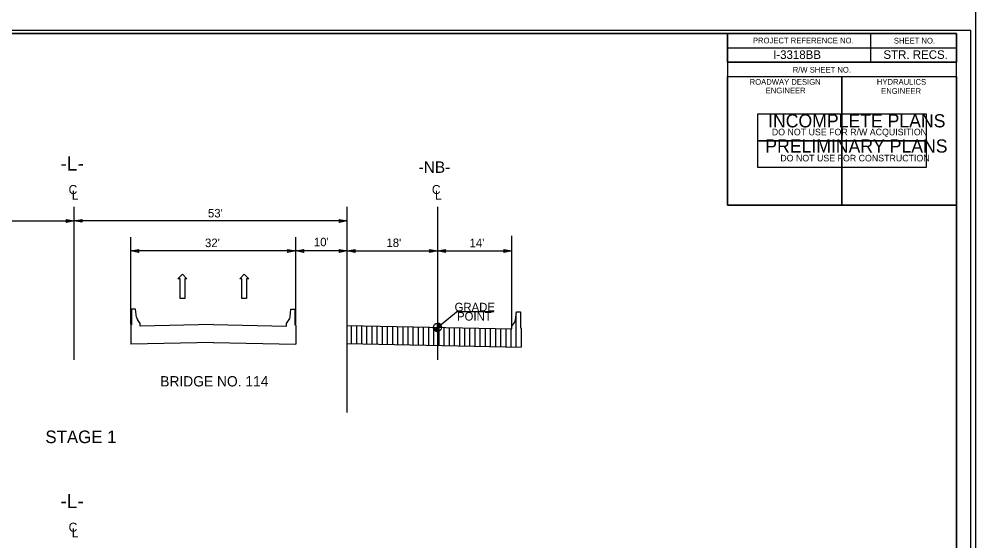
# Model space of a CAD drawing. Extents: x 2241081 to 2251104, y 658534 to 663427.
# Drawn here: x 2248483 to 2249319, y 659163 to 659619 of the extents above; entities that cross this region are included whole.
import ezdxf

# ---------------------------------------------------------------- set-up
doc = ezdxf.new("R2010")
doc.units = 0
for name, color, linetype in [('Prop Dimension Text', 7, 'Continuous'), ('Prop Lane Arrow CELL', 7, 'Continuous'), ('Prop Roadway Bridge', 7, 'Continuous'), ('Sheet Data Field CELL', 7, 'Continuous'), ('Sheet Plan CELL', 7, 'Continuous'), ('Sheet Plot Border Inside CELL', 7, 'Continuous'), ('Sheet Plot Border Outside CELL', 7, 'Continuous'), ('Sheet Sticker Incomplete CELL', 7, 'Continuous'), ('Sheet Sticker Preliminary CELL', 7, 'Continuous'), ('Typical Grade Point Symbol CELL', 7, 'Continuous'), ('Typical Terminator CELL', 7, 'Continuous'), ('Typical Text Centerline CELL', 7, 'Continuous'), ('Typical Text Grade Point CELL', 7, 'Continuous'), ('Typical Text Label CELL', 7, 'Continuous')]:
    doc.layers.add(name, color=color, linetype=linetype)

msp = doc.modelspace()

# ---------------------------------------------------------------- linework, layer by layer
at = {"layer": 'Prop Dimension Text'}
for p, q in [((2248769.6, 659351.53), (2248769.6, 659455.33)), ((2248310.6, 659442.91), (2248531.1, 659442.91)), ((2248769.6, 659442.91), (2248531.1, 659442.91)), ((2248580.6, 659352.28), (2248580.6, 659428.7)), ((2248724.6, 659352.28), (2248724.6, 659428.7)), ((2248913.6, 659351.23), (2248913.6, 659430.01)), ((2248724.6, 659416.65), (2248580.6, 659416.65)), ((2248769.6, 659416.65), (2248724.6, 659416.65)), ((2248769.6, 659416.65), (2248848.55, 659416.65)), ((2248848.55, 659416.65), (2248913.6, 659416.65)), ((2248917.42, 659332.79), (2248917.42, 659362.54)), ((2248769.6, 659275.49), (2248769.6, 659351.53)), ((2248773.42, 659335.79), (2248773.42, 659351.45)), ((2248777.92, 659335.69), (2248777.92, 659351.36)), ((2248782.42, 659335.6), (2248782.42, 659351.26)), ((2248786.92, 659335.51), (2248786.92, 659351.17)), ((2248791.42, 659335.41), (2248791.42, 659351.08)), ((2248795.92, 659335.32), (2248795.92, 659350.98)), ((2248800.42, 659335.23), (2248800.42, 659350.89)), ((2248804.92, 659335.13), (2248804.92, 659350.8)), ((2248809.42, 659335.04), (2248809.42, 659350.7)), ((2248813.92, 659334.95), (2248813.92, 659350.61)), ((2248818.42, 659334.85), (2248818.42, 659350.52)), ((2248822.92, 659334.76), (2248822.92, 659350.42)), ((2248827.42, 659334.66), (2248827.42, 659350.33)), ((2248831.92, 659334.57), (2248831.92, 659350.23)), ((2248836.42, 659334.48), (2248836.42, 659350.14)), ((2248840.92, 659334.38), (2248840.92, 659350.05)), ((2248845.42, 659334.29), (2248845.42, 659349.95)), ((2248849.92, 659334.2), (2248849.92, 659349.86)), ((2248854.42, 659334.1), (2248854.42, 659349.77)), ((2248858.92, 659334.01), (2248858.92, 659349.67)), ((2248863.42, 659333.92), (2248863.42, 659349.58)), ((2248867.92, 659333.82), (2248867.92, 659349.49)), ((2248872.42, 659333.73), (2248872.42, 659349.39)), ((2248876.92, 659333.63), (2248876.92, 659349.3)), ((2248881.42, 659333.54), (2248881.42, 659349.21)), ((2248885.92, 659333.45), (2248885.92, 659349.11)), ((2248890.42, 659333.35), (2248890.42, 659349.02)), ((2248894.92, 659333.26), (2248894.92, 659348.92)), ((2248899.42, 659333.17), (2248899.42, 659348.83)), ((2248903.92, 659333.07), (2248903.92, 659348.74)), ((2248908.42, 659332.98), (2248908.42, 659348.64)), ((2248912.92, 659332.89), (2248912.92, 659348.55))]:
    msp.add_line(p, q, dxfattribs=at)
at = {"layer": 'Prop Lane Arrow CELL'}
for p, q in [((2248621.75, 659392.35), (2248625.6, 659396.26)), ((2248623.61, 659392.35), (2248621.75, 659392.35)), ((2248623.61, 659374.99), (2248623.61, 659392.35)), ((2248625.6, 659396.26), (2248629.57, 659392.35)), ((2248629.57, 659392.35), (2248627.71, 659392.35)), ((2248627.71, 659392.35), (2248627.71, 659374.99)), ((2248675.75, 659392.35), (2248679.6, 659396.26)), ((2248677.61, 659392.35), (2248675.75, 659392.35)), ((2248677.61, 659374.99), (2248677.61, 659392.35)), ((2248679.6, 659396.26), (2248683.57, 659392.35)), ((2248683.57, 659392.35), (2248681.71, 659392.35)), ((2248681.71, 659392.35), (2248681.71, 659374.99)), ((2248627.71, 659374.99), (2248623.61, 659374.99)), ((2248681.71, 659374.99), (2248677.61, 659374.99))]:
    msp.add_line(p, q, dxfattribs=at)
at = {"layer": 'Prop Roadway Bridge'}
for p, q in [((2248581.42, 659365.89), (2248581.25, 659365.73)), ((2248581.25, 659365.73), (2248581.25, 659351.96)), ((2248584.57, 659365.89), (2248581.42, 659365.89)), ((2248584.76, 659365.71), (2248584.57, 659365.89)), ((2248585.49, 659358.74), (2248584.76, 659365.71)), ((2248719.71, 659358.74), (2248720.44, 659365.71)), ((2248720.44, 659365.71), (2248720.62, 659365.89)), ((2248720.62, 659365.89), (2248723.78, 659365.89)), ((2248723.78, 659365.89), (2248723.95, 659365.73)), ((2248723.95, 659365.73), (2248723.95, 659351.96)), ((2248916.77, 659356.33), (2248917.5, 659363.3)), ((2248917.5, 659363.3), (2248917.68, 659363.48)), ((2248917.68, 659363.48), (2248920.84, 659363.48)), ((2248920.84, 659363.48), (2248921, 659363.32)), ((2248921, 659363.32), (2248921, 659349.54)), ((2248580.93, 659351.96), (2248580.6, 659351.63)), ((2248580.6, 659351.63), (2248580.6, 659349.34)), ((2248581.25, 659351.96), (2248580.93, 659351.96)), ((2248588.66, 659353.26), (2248586.25, 659356.7)), ((2248588.66, 659350.95), (2248588.66, 659353.26)), ((2248652.6, 659352.28), (2248588.66, 659350.95)), ((2248652.6, 659352.28), (2248716.54, 659350.95)), ((2248716.54, 659353.26), (2248718.94, 659356.7)), ((2248716.54, 659350.95), (2248716.54, 659353.26)), ((2248723.95, 659351.96), (2248724.27, 659351.96)), ((2248724.27, 659351.96), (2248724.6, 659351.63)), ((2248724.6, 659351.63), (2248724.6, 659349.34)), ((2248769.6, 659351.53), (2248913.6, 659348.54)), ((2248913.6, 659350.85), (2248916, 659354.28)), ((2248913.6, 659348.54), (2248913.6, 659350.85)), ((2248921, 659349.54), (2248921.33, 659349.54)), ((2248921.33, 659349.54), (2248921.66, 659349.22)), ((2248580.6, 659349.34), (2248580.6, 659335.12)), ((2248724.6, 659349.34), (2248724.6, 659335.12)), ((2248921.66, 659349.22), (2248921.66, 659346.93)), ((2248921.66, 659346.93), (2248921.66, 659332.7)), ((2248652.92, 659336.62), (2248580.6, 659335.12)), ((2248652.6, 659336.61), (2248724.6, 659335.12)), ((2248769.6, 659335.87), (2248921.66, 659332.7))]:
    msp.add_line(p, q, dxfattribs=at)
for centre, start, end in [((2248589.82, 659359.19), 186.011, 214.99123), ((2248715.38, 659359.19), 325.00863, 353.98887), ((2248912.43, 659356.78), 325.00863, 353.98887)]:
    msp.add_arc(centre, 4.36, start, end, dxfattribs=at)
at = {"layer": 'Sheet Plan CELL'}
for p, q in [((2249226.97, 659606.71), (2249227.02, 659581.71)), ((2249101.94, 659594.24), (2249301.99, 659594.23)), ((2249101.96, 659581.7), (2249301.99, 659581.73)), ((2249101.96, 659581.7), (2249301.99, 659581.73)), ((2249101.96, 659581.7), (2249101.96, 659569.21)), ((2249202.01, 659569.21), (2249202.02, 659456.75))]:
    msp.add_line(p, q, dxfattribs=at)
for points in [[(2247801.99, 658556.78), (2247801.97, 659606.75), (2249101.96, 659606.79), (2249101.97, 659456.73), (2249302.01, 659456.71), (2249302, 658556.78)], [(2249302.03, 659606.78), (2247801.99, 659606.78), (2247801.99, 658556.78), (2249302, 658556.78)], [(2249101.96, 659606.79), (2249302.03, 659606.78), (2249301.99, 659581.73), (2249101.96, 659581.7)], [(2249101.96, 659569.21), (2249202.01, 659569.21), (2249202.01, 659456.7), (2249101.97, 659456.73)], [(2249202.01, 659569.21), (2249301.99, 659569.23), (2249302.01, 659456.71), (2249202.01, 659456.7)]]:
    msp.add_lwpolyline(points, close=True, dxfattribs=at)
at = {"layer": 'Sheet Plot Border Inside CELL'}
msp.add_lwpolyline([(2247648.5, 658554.27), (2249314.49, 658554.28), (2249314.51, 659609.26), (2247648.51, 659609.27)], close=True, dxfattribs=at)
at = {"layer": 'Sheet Plot Border Outside CELL'}
msp.add_lwpolyline([(2247635.5, 658534.27), (2249319, 658534.26), (2249319.01, 659629.26), (2247635.51, 659629.27)], close=True, dxfattribs=at)
at = {"layer": 'Sheet Sticker Incomplete CELL'}
msp.add_lwpolyline([(2249128.51, 659512.96), (2249128.51, 659536.46), (2249275.51, 659536.46), (2249275.51, 659512.96)], close=True, dxfattribs=at)
at = {"layer": 'Sheet Sticker Preliminary CELL'}
msp.add_lwpolyline([(2249128.51, 659489.46), (2249128.51, 659512.96), (2249275.51, 659512.96), (2249275.51, 659489.46)], close=True, dxfattribs=at)
at = {"layer": 'Typical Grade Point Symbol CELL'}
for p, q in [((2248848.55, 659349.89), (2248865.24, 659363.34)), ((2248844.97, 659349.89), (2248848.55, 659349.89)), ((2248848.55, 659353.47), (2248848.55, 659349.89)), ((2248848.55, 659349.89), (2248848.55, 659353.47)), ((2248848.55, 659349.89), (2248848.55, 659346.31)), ((2248852.13, 659349.89), (2248848.55, 659349.89))]:
    msp.add_line(p, q, dxfattribs=at)
for points in [[(2248845.01, 659349.38), (2248845.01, 659349.89)], [(2248845.08, 659349.01), (2248845.08, 659349.89)], [(2248845.15, 659348.77), (2248845.15, 659349.89)], [(2248845.22, 659348.57), (2248845.22, 659349.89)], [(2248845.29, 659348.4), (2248845.29, 659349.89)], [(2248845.36, 659348.25), (2248845.36, 659349.89)], [(2248845.44, 659348.12), (2248845.44, 659349.89)], [(2248845.51, 659348), (2248845.51, 659349.89)], [(2248845.58, 659347.89), (2248845.58, 659349.89)], [(2248845.65, 659347.79), (2248845.65, 659349.89)], [(2248845.72, 659347.69), (2248845.72, 659349.89)], [(2248845.79, 659347.61), (2248845.79, 659349.89)], [(2248845.87, 659347.52), (2248845.87, 659349.89)], [(2248845.94, 659347.44), (2248845.94, 659349.89)], [(2248846.01, 659347.37), (2248846.01, 659349.89)], [(2248846.08, 659347.29), (2248846.08, 659349.89)], [(2248846.15, 659347.23), (2248846.15, 659349.89)], [(2248846.22, 659347.17), (2248846.22, 659349.89)], [(2248846.29, 659347.1), (2248846.29, 659349.89)], [(2248846.37, 659347.05), (2248846.37, 659349.89)], [(2248846.44, 659347), (2248846.44, 659349.89)], [(2248846.51, 659346.95), (2248846.51, 659349.89)], [(2248846.58, 659346.9), (2248846.58, 659349.89)], [(2248846.65, 659346.85), (2248846.65, 659349.89)], [(2248846.72, 659346.81), (2248846.72, 659349.89)], [(2248846.8, 659346.77), (2248846.8, 659349.89)], [(2248846.87, 659346.73), (2248846.87, 659349.89)], [(2248846.94, 659346.69), (2248846.94, 659349.89)], [(2248847.01, 659346.66), (2248847.01, 659349.89)], [(2248847.08, 659346.63), (2248847.08, 659349.89)], [(2248847.15, 659346.59), (2248847.15, 659349.89)], [(2248847.23, 659346.56), (2248847.23, 659349.89)], [(2248847.3, 659346.53), (2248847.3, 659349.89)], [(2248847.37, 659346.51), (2248847.37, 659349.89)], [(2248847.44, 659346.48), (2248847.44, 659349.89)], [(2248847.51, 659346.46), (2248847.51, 659349.89)], [(2248847.58, 659346.44), (2248847.58, 659349.89)], [(2248847.66, 659346.42), (2248847.66, 659349.89)], [(2248847.73, 659346.4), (2248847.73, 659349.89)], [(2248847.8, 659346.39), (2248847.8, 659349.89)], [(2248847.87, 659346.37), (2248847.87, 659349.89)], [(2248847.94, 659346.36), (2248847.94, 659349.89)], [(2248848.01, 659346.35), (2248848.01, 659349.89)], [(2248848.09, 659346.34), (2248848.09, 659349.89)], [(2248848.16, 659346.33), (2248848.16, 659349.89)], [(2248848.23, 659346.32), (2248848.23, 659349.89)], [(2248848.3, 659346.32), (2248848.3, 659349.89)], [(2248848.37, 659346.32), (2248848.37, 659349.89)], [(2248848.44, 659346.31), (2248848.44, 659349.89)], [(2248848.51, 659346.31), (2248848.51, 659346.31), (2248848.51, 659349.89)], [(2248848.6, 659349.89), (2248848.6, 659353.47), (2248848.6, 659353.47)], [(2248848.67, 659349.89), (2248848.67, 659353.47)], [(2248848.75, 659349.89), (2248848.75, 659353.46)], [(2248848.82, 659349.89), (2248848.82, 659353.46)], [(2248848.89, 659349.89), (2248848.89, 659353.45)], [(2248848.96, 659349.89), (2248848.96, 659353.45)], [(2248849.03, 659349.89), (2248849.03, 659353.44)], [(2248849.1, 659349.89), (2248849.1, 659353.42)], [(2248849.18, 659349.89), (2248849.18, 659353.41)], [(2248849.25, 659349.89), (2248849.25, 659353.4)], [(2248849.32, 659349.89), (2248849.32, 659353.38)], [(2248849.39, 659349.89), (2248849.39, 659353.37)], [(2248849.46, 659349.89), (2248849.46, 659353.35)], [(2248849.53, 659349.89), (2248849.53, 659353.33)], [(2248849.61, 659349.89), (2248849.61, 659353.31)], [(2248849.68, 659349.89), (2248849.68, 659353.29)], [(2248849.75, 659349.89), (2248849.75, 659353.26)], [(2248849.82, 659349.89), (2248849.82, 659353.24)], [(2248849.89, 659349.89), (2248849.89, 659353.21)], [(2248849.96, 659349.89), (2248849.96, 659353.18)], [(2248850.03, 659349.89), (2248850.03, 659353.14)], [(2248850.11, 659349.89), (2248850.11, 659353.11)], [(2248850.18, 659349.89), (2248850.18, 659353.08)], [(2248850.25, 659349.89), (2248850.25, 659353.04)], [(2248850.32, 659349.89), (2248850.32, 659353)], [(2248850.39, 659349.89), (2248850.39, 659352.96)], [(2248850.46, 659349.89), (2248850.46, 659352.91)], [(2248850.54, 659349.89), (2248850.54, 659352.86)], [(2248850.61, 659349.89), (2248850.61, 659352.82)], [(2248850.68, 659349.89), (2248850.68, 659352.77)], [(2248850.75, 659349.89), (2248850.75, 659352.71)], [(2248850.82, 659349.89), (2248850.82, 659352.66)], [(2248850.89, 659349.89), (2248850.89, 659352.59)], [(2248850.97, 659349.89), (2248850.97, 659352.53)], [(2248851.04, 659349.89), (2248851.04, 659352.47)], [(2248851.11, 659349.89), (2248851.11, 659352.4)], [(2248851.18, 659349.89), (2248851.18, 659352.32)], [(2248851.25, 659349.89), (2248851.25, 659352.24)], [(2248851.32, 659349.89), (2248851.32, 659352.15)], [(2248851.4, 659349.89), (2248851.4, 659352.06)], [(2248851.47, 659349.89), (2248851.47, 659351.97)], [(2248851.54, 659349.89), (2248851.54, 659351.86)], [(2248851.61, 659349.89), (2248851.61, 659351.75)], [(2248851.68, 659349.89), (2248851.68, 659351.62)], [(2248851.75, 659349.89), (2248851.75, 659351.49)], [(2248851.83, 659349.89), (2248851.83, 659351.34)], [(2248851.9, 659349.89), (2248851.9, 659351.17)], [(2248851.97, 659349.89), (2248851.97, 659350.96)], [(2248852.04, 659349.89), (2248852.04, 659350.7)], [(2248852.11, 659349.89), (2248852.11, 659350.28)]]:
    msp.add_lwpolyline(points, dxfattribs=at)
msp.add_circle((2248848.55, 659349.89), 3.58, dxfattribs=at)
for start, end in [(179.99048, 269.99048), (359.99048, 89.99048)]:
    msp.add_arc((2248848.55, 659349.89), 3.58, start, end, dxfattribs=at)
at = {"layer": 'Typical Terminator CELL'}
for points in [[(2248524.07, 659444.12), (2248531.1, 659442.91), (2248524.03, 659441.66), (2248524.93, 659442.91)], [(2248538.13, 659441.7), (2248531.1, 659442.91), (2248538.17, 659444.16), (2248537.27, 659442.91)], [(2248762.57, 659444.12), (2248769.6, 659442.91), (2248762.53, 659441.66), (2248763.43, 659442.91)], [(2248587.63, 659415.43), (2248580.6, 659416.65), (2248587.67, 659417.9), (2248586.77, 659416.65)], [(2248717.57, 659417.86), (2248724.6, 659416.65), (2248717.53, 659415.4), (2248718.43, 659416.65)], [(2248731.63, 659415.43), (2248724.6, 659416.65), (2248731.67, 659417.9), (2248730.77, 659416.65)], [(2248762.57, 659417.86), (2248769.6, 659416.65), (2248762.53, 659415.4), (2248763.43, 659416.65)], [(2248776.63, 659415.43), (2248769.6, 659416.65), (2248776.67, 659417.9), (2248775.77, 659416.65)], [(2248841.52, 659417.86), (2248848.55, 659416.65), (2248841.48, 659415.4), (2248842.38, 659416.65)], [(2248855.58, 659415.43), (2248848.55, 659416.65), (2248855.62, 659417.9), (2248854.72, 659416.65)], [(2248906.57, 659417.86), (2248913.6, 659416.65), (2248906.53, 659415.4), (2248907.43, 659416.65)]]:
    msp.add_lwpolyline(points, close=True, dxfattribs=at)
at = {"layer": 'Typical Text Centerline CELL'}
for p, q in [((2248531.1, 659321.64), (2248531.1, 659455.33)), ((2248848.55, 659455.33), (2248848.55, 659321.64))]:
    msp.add_line(p, q, dxfattribs=at)
at = {"layer": 'Typical Text Grade Point CELL'}
msp.add_line((2248897.75, 659363.34), (2248865.24, 659363.34), dxfattribs=at)

# ---------------------------------------------------------------- texts
at = {"layer": 'Prop Dimension Text'}
for s, height, rotation, p in [('-L-', 12.5, 0.03489, (2248519.02, 659486.96)), ('-NB-', 10.024, 0.03489, (2248832.13, 659484.91)), ("53'", 7.425, 359.99993, (2248647.94, 659445.95)), ("32'", 7.425, 359.99993, (2248645.38, 659420.01)), ("10'", 7.425, 359.99993, (2248740.55, 659420.77)), ("18'", 7.425, 359.99993, (2248803.94, 659420.06)), ("14'", 7.425, 359.99993, (2248876.57, 659419.91)), ('BRIDGE NO. 114', 9.0214, 359.99993, (2248606.24, 659298.23)), ('-L-', 12.5, 0.03489, (2248519.02, 659191.86))]:
    msp.add_text(s, height=height, rotation=rotation, dxfattribs=at).set_placement(p)
at = {"layer": 'Sheet Data Field CELL'}
for s, p in [('I-3318BB', (2249141.83, 659584.46)), ('STR. RECS.', (2249238.26, 659584.53))]:
    msp.add_text(s, height=7.5, rotation=359.99994, dxfattribs=at).set_placement(p)
at = {"layer": 'Sheet Plan CELL'}
for s, height, p in [('PROJECT REFERENCE NO.', 5.0001, (2249124.16, 659598.06)), ('SHEET NO.', 5, (2249247.32, 659597.95)), ('R/W SHEET NO.', 5.0001, (2249158.96, 659572.51)), ('ROADWAY DESIGN', 5.0001, (2249121.33, 659561.91)), ('HYDRAULICS', 5, (2249232.47, 659561.94)), ('ENGINEER', 5, (2249135.32, 659554.38)), ('ENGINEER', 5, (2249236.23, 659553.98))]:
    msp.add_text(s, height=height, rotation=359.99994, dxfattribs=at).set_placement(p)
at = {"layer": 'Sheet Sticker Incomplete CELL'}
for s, height, p in [('INCOMPLETE PLANS', 11.52, (2249137.46, 659524.66)), ('DO NOT USE FOR R/W ACQUISITION', 5.76, (2249140.71, 659517.71))]:
    msp.add_text(s, height=height, rotation=359.99993, dxfattribs=at).set_placement(p)
at = {"layer": 'Sheet Sticker Preliminary CELL'}
for s, height, p in [('PRELIMINARY PLANS', 11.52, (2249135.01, 659502.61)), ('DO NOT USE FOR CONSTRUCTION', 5.76, (2249148.11, 659494.91))]:
    msp.add_text(s, height=height, rotation=359.99993, dxfattribs=at).set_placement(p)
at = {"layer": 'Typical Text Centerline CELL'}
for s, rotation, p in [('C', 359.99993, (2248526.18, 659466.39)), ('L', 359.94683, (2248528.91, 659461.43)), ('C', 359.99993, (2248843.63, 659466.39)), ('L', 359.94683, (2248846.36, 659461.43)), ('C', 359.99993, (2248526.18, 659171.28)), ('L', 359.94683, (2248528.91, 659166.33))]:
    msp.add_text(s, height=7.88, rotation=rotation, dxfattribs=at).set_placement(p)
at = {"layer": 'Typical Text Grade Point CELL'}
for s, p in [('GRADE', (2248863.45, 659363.9)), ('POINT', (2248865.59, 659355.8))]:
    msp.add_text(s, height=7.425, rotation=359.99993, dxfattribs=at).set_placement(p)
at = {"layer": 'Typical Text Label CELL'}
msp.add_text('STAGE 1', height=11.011, dxfattribs=at).set_placement((2248505.87, 659248.69))

doc.saveas('drawing.dxf')
